Omron CX-Programmer project 新工程 (CX-Programmer 4.01)

# PLC 新PLC1: CPM2* 

## Program 新程序1 (no task)

### Section 段1

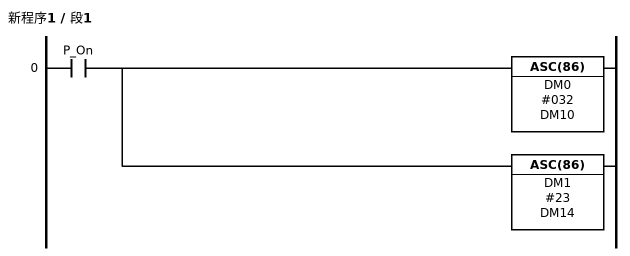
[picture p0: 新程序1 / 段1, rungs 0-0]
; rung 0
LD P_On
ASC(86) DM0 #032 DM10
ASC(86) DM1 #23 DM14

### Section END
; rung 0
END(01)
